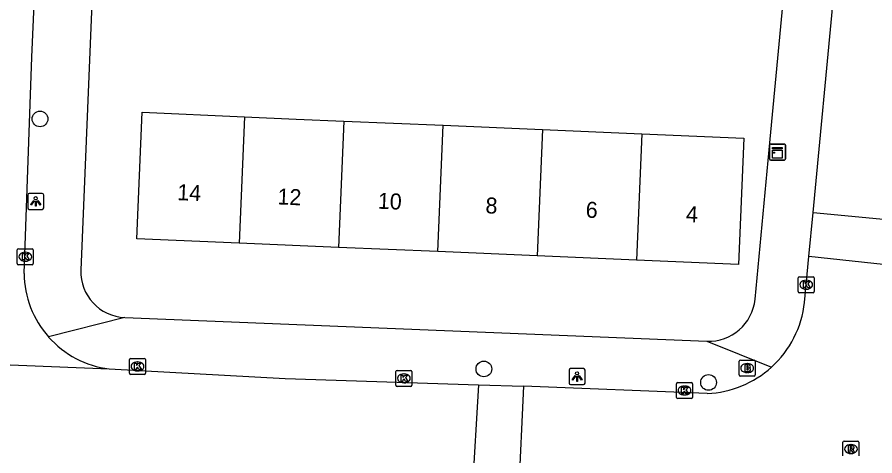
# Model space of a CAD drawing. Extents: x 161355 to 162026, y 386504 to 387459.
# Drawn here: x 161733.1 to 161786.7, y 386642.6 to 386670 of the extents above; entities that cross this region are included whole.
import ezdxf

# ---------------------------------------------------------------- set-up
doc = ezdxf.new("R2010")
doc.units = 0
for name, color, linetype in [('IMGEO_Boom', 7, 'Continuous'), ('IMGEO_Brandkraan', 7, 'Continuous'), ('IMGEO_Kast', 7, 'Continuous'), ('IMGEO_Kolk', 7, 'Continuous'), ('IMGEO_Lichtpunt', 7, 'Continuous'), ('IMGEO_Muur', 7, 'Continuous'), ('IMGEO_Pand', 7, 'Continuous'), ('IMGEO_Pand_nummerreeks', 7, 'Continuous'), ('IMGEO_Rijbaan_lokaal_open', 7, 'Continuous'), ('IMGEO_Rioolput', 7, 'Continuous'), ('IMGEO_Voetpad_open', 7, 'Continuous')]:
    doc.layers.add(name, color=color, linetype=linetype)

msp = doc.modelspace()

# ---------------------------------------------------------------- linework, layer by layer
at = {"layer": 'IMGEO_Boom'}
for centre in [(161734.57, 386663.656), (161762.276, 386648.038), (161776.299, 386647.194)]:
    msp.add_circle(centre, 0.489, dxfattribs=at)
at = {"layer": 'IMGEO_Brandkraan'}
for p, q in [((161778.287, 386648.59), (161779.139, 386648.59)), ((161778.212, 386647.664), (161778.212, 386648.516)), ((161778.7, 386648.37), (161778.725, 386648.37)), ((161779.213, 386648.516), (161779.213, 386647.664)), ((161779.139, 386647.59), (161778.287, 386647.59)), ((161778.723, 386647.81), (161778.698, 386647.81))]:
    msp.add_line(p, q, dxfattribs=at)
for points in [[(161778.287, 386648.59), (161779.139, 386648.59)], [(161778.212, 386647.664), (161778.212, 386648.516)], [(161778.56, 386648.29), (161778.56, 386647.89), (161778.773, 386647.89)], [(161778.791, 386648.29), (161778.56, 386648.29)], [(161778.739, 386648.209), (161778.685, 386648.209), (161778.685, 386648.133)], [(161778.685, 386648.133), (161778.738, 386648.133)], [(161778.747, 386648.057), (161778.685, 386648.057), (161778.685, 386647.976)], [(161779.213, 386648.516), (161779.213, 386647.664)], [(161779.139, 386647.59), (161778.287, 386647.59)], [(161778.685, 386647.976), (161778.747, 386647.976)]]:
    msp.add_lwpolyline(points, dxfattribs=at)
for centre, radius, start, end in [((161778.289, 386648.514), 0.0765, 91.552, 178.448), ((161778.289, 386648.514), 0.0765, 91.552, 178.448), ((161779.137, 386648.514), 0.0765, 1.552, 88.448), ((161779.137, 386648.514), 0.0765, 1.552, 88.448), ((161778.74, 386648.171), 0.0379, 267.8285, 90.9355), ((161778.748, 386648.016), 0.0404, 269.8759, 90.5077), ((161778.795, 386648.145), 0.145, 59.4692, 91.5367), ((161778.82, 386648.192), 0.0922, 285.5137, 58.1501), ((161778.825, 386648), 0.105, 301.3115, 78.989), ((161778.289, 386647.666), 0.0765, 181.552, 268.448), ((161778.289, 386647.666), 0.0765, 181.552, 268.448), ((161778.779, 386648.141), 0.251, 268.6676, 293.5347), ((161779.137, 386647.666), 0.0765, 271.552, 358.448), ((161779.137, 386647.666), 0.0765, 271.552, 358.448)]:
    msp.add_arc(centre, radius, start, end, dxfattribs=at)
for centre, major_axis, ratio, start_param, end_param in [((161778.699, 386648.09), (-0.387, 0.002), 0.722429, 4.712389, 7.853982), ((161778.724, 386648.09), (-0.39, 0.002), 0.717154, 1.570796, 4.712389)]:
    msp.add_ellipse(centre, major_axis=major_axis, ratio=ratio, start_param=start_param, end_param=end_param, dxfattribs=at)
at = {"layer": 'IMGEO_Kast'}
for p, q in [((161780.107, 386661.163), (161780.107, 386662.004)), ((161780.107, 386662.004), (161780.107, 386661.163)), ((161780.182, 386662.088), (161781.023, 386662.088)), ((161781.023, 386662.088), (161780.182, 386662.088)), ((161781.107, 386662.013), (161781.107, 386661.172)), ((161781.107, 386661.172), (161781.107, 386662.013)), ((161781.032, 386661.088), (161780.191, 386661.088)), ((161780.191, 386661.088), (161781.032, 386661.088))]:
    msp.add_line(p, q, dxfattribs=at)
for points in [[(161780.302, 386661.878), (161780.902, 386661.878), (161780.902, 386661.793), (161780.302, 386661.793), (161780.302, 386661.878)], [(161780.302, 386661.703), (161780.902, 386661.703), (161780.902, 386661.214), (161780.302, 386661.214), (161780.302, 386661.703)]]:
    msp.add_lwpolyline(points, dxfattribs=at)
msp.add_circle((161780.386, 386661.552), 0.0377, dxfattribs=at)
for centre, start, end in [((161780.185, 386662.01), 92.4484, 184.2845), ((161780.185, 386662.01), 92.4484, 184.2845), ((161781.029, 386662.01), 2.4484, 94.2845), ((161781.029, 386662.01), 2.4484, 94.2845), ((161780.185, 386661.166), 182.4484, 274.2845), ((161780.185, 386661.166), 182.4484, 274.2845), ((161781.029, 386661.166), 272.4484, 4.2845), ((161781.029, 386661.166), 272.4484, 4.2845)]:
    msp.add_arc(centre, 0.0779, start, end, dxfattribs=at)
at = {"layer": 'IMGEO_Kolk'}
for p, q in [((161733.227, 386655.546), (161734.079, 386655.546)), ((161733.152, 386654.62), (161733.152, 386655.472)), ((161733.64, 386655.326), (161733.665, 386655.326)), ((161734.153, 386655.472), (161734.153, 386654.62)), ((161734.079, 386654.546), (161733.227, 386654.546)), ((161733.663, 386654.766), (161733.638, 386654.766)), ((161781.896, 386652.876), (161781.896, 386653.728)), ((161781.971, 386653.802), (161782.823, 386653.802)), ((161782.384, 386653.582), (161782.409, 386653.582)), ((161782.897, 386653.728), (161782.897, 386652.876)), ((161782.407, 386653.022), (161782.382, 386653.022)), ((161782.823, 386652.802), (161781.971, 386652.802)), ((161740.154, 386647.771), (161740.154, 386648.623)), ((161740.229, 386648.697), (161741.081, 386648.697)), ((161741.155, 386648.623), (161741.155, 386647.771)), ((161740.642, 386648.477), (161740.667, 386648.477)), ((161741.081, 386647.697), (161740.229, 386647.697)), ((161740.665, 386647.917), (161740.64, 386647.917)), ((161756.783, 386647.026), (161756.783, 386647.878)), ((161756.858, 386647.952), (161757.71, 386647.952)), ((161757.271, 386647.732), (161757.296, 386647.732)), ((161757.784, 386647.878), (161757.784, 386647.026)), ((161757.294, 386647.172), (161757.269, 386647.172)), ((161774.3, 386646.266), (161774.3, 386647.118)), ((161774.375, 386647.192), (161775.227, 386647.192)), ((161774.788, 386646.972), (161774.813, 386646.972)), ((161775.301, 386647.118), (161775.301, 386646.266)), ((161757.71, 386646.952), (161756.858, 386646.952)), ((161775.227, 386646.192), (161774.375, 386646.192)), ((161774.811, 386646.412), (161774.786, 386646.412))]:
    msp.add_line(p, q, dxfattribs=at)
for points in [[(161733.227, 386655.546), (161734.079, 386655.546)], [(161733.152, 386654.62), (161733.152, 386655.472)], [(161733.473, 386655.246), (161733.596, 386655.246), (161733.596, 386655.095), (161733.726, 386655.246), (161733.89, 386655.246), (161733.744, 386655.095), (161733.897, 386654.846), (161733.745, 386654.846), (161733.66, 386655.01), (161733.596, 386654.943), (161733.596, 386654.846), (161733.473, 386654.846), (161733.473, 386655.246)], [(161734.153, 386655.472), (161734.153, 386654.62)], [(161734.079, 386654.546), (161733.227, 386654.546)], [(161781.896, 386652.876), (161781.896, 386653.728)], [(161781.971, 386653.802), (161782.823, 386653.802)], [(161782.217, 386653.502), (161782.34, 386653.502), (161782.34, 386653.351), (161782.47, 386653.502), (161782.634, 386653.502), (161782.488, 386653.351), (161782.641, 386653.102), (161782.489, 386653.102), (161782.404, 386653.266), (161782.34, 386653.199), (161782.34, 386653.102), (161782.217, 386653.102), (161782.217, 386653.502)], [(161782.897, 386653.728), (161782.897, 386652.876)], [(161782.823, 386652.802), (161781.971, 386652.802)], [(161740.154, 386647.771), (161740.154, 386648.623)], [(161740.229, 386648.697), (161741.081, 386648.697)], [(161741.155, 386648.623), (161741.155, 386647.771)], [(161740.475, 386648.397), (161740.598, 386648.397), (161740.598, 386648.246), (161740.728, 386648.397), (161740.892, 386648.397), (161740.746, 386648.246), (161740.899, 386647.997), (161740.747, 386647.997), (161740.662, 386648.161), (161740.598, 386648.094), (161740.598, 386647.997), (161740.475, 386647.997), (161740.475, 386648.397)], [(161741.081, 386647.697), (161740.229, 386647.697)], [(161756.783, 386647.026), (161756.783, 386647.878)], [(161756.858, 386647.952), (161757.71, 386647.952)], [(161757.104, 386647.652), (161757.227, 386647.652), (161757.227, 386647.501), (161757.357, 386647.652), (161757.521, 386647.652), (161757.375, 386647.501), (161757.528, 386647.252), (161757.376, 386647.252), (161757.291, 386647.416), (161757.227, 386647.349), (161757.227, 386647.252), (161757.104, 386647.252), (161757.104, 386647.652)], [(161757.784, 386647.878), (161757.784, 386647.026)], [(161774.3, 386646.266), (161774.3, 386647.118)], [(161774.375, 386647.192), (161775.227, 386647.192)], [(161775.301, 386647.118), (161775.301, 386646.266)], [(161757.71, 386646.952), (161756.858, 386646.952)], [(161774.621, 386646.892), (161774.744, 386646.892), (161774.744, 386646.741), (161774.874, 386646.892), (161775.038, 386646.892), (161774.892, 386646.741), (161775.045, 386646.492), (161774.893, 386646.492), (161774.808, 386646.656), (161774.744, 386646.589), (161774.744, 386646.492), (161774.621, 386646.492), (161774.621, 386646.892)], [(161775.227, 386646.192), (161774.375, 386646.192)]]:
    msp.add_lwpolyline(points, dxfattribs=at)
for centre, start, end in [((161733.229, 386655.47), 91.552, 178.448), ((161733.229, 386655.47), 91.552, 178.448), ((161734.077, 386655.47), 1.552, 88.448), ((161734.077, 386655.47), 1.552, 88.448), ((161733.229, 386654.622), 181.552, 268.448), ((161733.229, 386654.622), 181.552, 268.448), ((161734.077, 386654.622), 271.552, 358.448), ((161734.077, 386654.622), 271.552, 358.448), ((161781.973, 386653.726), 91.552, 178.448), ((161781.973, 386653.726), 91.552, 178.448), ((161782.821, 386653.726), 1.552, 88.448), ((161782.821, 386653.726), 1.552, 88.448), ((161781.973, 386652.878), 181.552, 268.448), ((161781.973, 386652.878), 181.552, 268.448), ((161782.821, 386652.878), 271.552, 358.448), ((161782.821, 386652.878), 271.552, 358.448), ((161740.231, 386648.621), 91.552, 178.448), ((161740.231, 386648.621), 91.552, 178.448), ((161741.079, 386648.621), 1.552, 88.448), ((161741.079, 386648.621), 1.552, 88.448), ((161740.231, 386647.773), 181.552, 268.448), ((161740.231, 386647.773), 181.552, 268.448), ((161741.079, 386647.773), 271.552, 358.448), ((161741.079, 386647.773), 271.552, 358.448), ((161756.86, 386647.876), 91.552, 178.448), ((161756.86, 386647.876), 91.552, 178.448), ((161757.708, 386647.876), 1.552, 88.448), ((161757.708, 386647.876), 1.552, 88.448), ((161756.86, 386647.028), 181.552, 268.448), ((161756.86, 386647.028), 181.552, 268.448), ((161757.708, 386647.028), 271.552, 358.448), ((161757.708, 386647.028), 271.552, 358.448), ((161774.377, 386647.116), 91.552, 178.448), ((161774.377, 386647.116), 91.552, 178.448), ((161775.225, 386647.116), 1.552, 88.448), ((161775.225, 386647.116), 1.552, 88.448), ((161774.377, 386646.268), 181.552, 268.448), ((161774.377, 386646.268), 181.552, 268.448), ((161775.225, 386646.268), 271.552, 358.448), ((161775.225, 386646.268), 271.552, 358.448)]:
    msp.add_arc(centre, 0.0765, start, end, dxfattribs=at)
for centre, major_axis, ratio, start_param, end_param in [((161733.639, 386655.046), (-0.387, 0.002), 0.722429, 4.712389, 7.853982), ((161733.664, 386655.046), (-0.39, 0.002), 0.717154, 1.570796, 4.712389), ((161782.383, 386653.302), (-0.387, 0.002), 0.722429, 4.712389, 7.853982), ((161782.408, 386653.302), (-0.39, 0.002), 0.717154, 1.570796, 4.712389), ((161740.641, 386648.197), (-0.387, 0.002), 0.722429, 4.712389, 7.853982), ((161740.666, 386648.197), (-0.39, 0.002), 0.717154, 1.570796, 4.712389), ((161757.27, 386647.452), (-0.387, 0.002), 0.722429, 4.712389, 7.853982), ((161757.295, 386647.452), (-0.39, 0.002), 0.717154, 1.570796, 4.712389), ((161774.787, 386646.692), (-0.387, 0.002), 0.722429, 4.712389, 7.853982), ((161774.812, 386646.692), (-0.39, 0.002), 0.717154, 1.570796, 4.712389)]:
    msp.add_ellipse(centre, major_axis=major_axis, ratio=ratio, start_param=start_param, end_param=end_param, dxfattribs=at)
at = {"layer": 'IMGEO_Lichtpunt'}
for p, q in [((161733.803, 386658.904), (161733.803, 386658.097)), ((161733.803, 386658.904), (161733.803, 386658.097)), ((161734.705, 386658.999), (161733.897, 386658.999)), ((161734.705, 386658.999), (161733.897, 386658.999)), ((161734.799, 386658.097), (161734.799, 386658.904)), ((161734.799, 386658.097), (161734.799, 386658.904)), ((161733.897, 386658.003), (161734.705, 386658.003)), ((161733.897, 386658.003), (161734.705, 386658.003)), ((161768.495, 386648.062), (161767.687, 386648.062)), ((161768.495, 386648.062), (161767.687, 386648.062)), ((161767.593, 386647.967), (161767.593, 386647.16)), ((161767.593, 386647.967), (161767.593, 386647.16)), ((161768.589, 386647.16), (161768.589, 386647.967)), ((161768.589, 386647.16), (161768.589, 386647.967)), ((161767.687, 386647.066), (161768.495, 386647.066)), ((161767.687, 386647.066), (161768.495, 386647.066))]:
    msp.add_line(p, q, dxfattribs=at)
for points in [[(161734.177, 386658.568), (161734.216, 386658.54), (161734.028, 386658.278), (161733.99, 386658.305), (161734.177, 386658.568)], [(161734.279, 386658.52), (161734.326, 386658.52), (161734.326, 386658.198), (161734.279, 386658.198), (161734.279, 386658.52)], [(161734.389, 386658.54), (161734.427, 386658.567), (161734.614, 386658.305), (161734.575, 386658.277), (161734.389, 386658.54)], [(161767.967, 386647.631), (161768.006, 386647.603), (161767.818, 386647.341), (161767.78, 386647.368), (161767.967, 386647.631)], [(161768.069, 386647.583), (161768.116, 386647.583), (161768.116, 386647.261), (161768.069, 386647.261), (161768.069, 386647.583)], [(161768.179, 386647.603), (161768.217, 386647.63), (161768.404, 386647.368), (161768.365, 386647.34), (161768.179, 386647.603)]]:
    msp.add_lwpolyline(points, dxfattribs=at)
for centre in [(161734.302, 386658.702), (161768.092, 386647.765)]:
    msp.add_circle(centre, 0.0994, dxfattribs=at)
for centre, start, end in [((161733.897, 386658.904), 90, 180), ((161733.897, 386658.904), 90, 180), ((161734.705, 386658.904), 0, 90), ((161734.705, 386658.904), 0, 90), ((161733.897, 386658.097), 180, 270), ((161733.897, 386658.097), 180, 270), ((161734.705, 386658.097), 270, 0), ((161734.705, 386658.097), 270, 360), ((161767.687, 386647.967), 90, 180), ((161767.687, 386647.967), 90, 180), ((161768.495, 386647.967), 0, 90), ((161768.495, 386647.967), 0, 90), ((161767.687, 386647.16), 180, 270), ((161767.687, 386647.16), 180, 270), ((161768.495, 386647.16), 270, 0), ((161768.495, 386647.16), 270, 360)]:
    msp.add_arc(centre, 0.0946, start, end, dxfattribs=at)
at = {"layer": 'IMGEO_Muur'}
msp.add_lwpolyline([(161780.147, 386662.39), (161781.003, 386671.42)], dxfattribs=at)
at = {"layer": 'IMGEO_Pand'}
for points in [[(161746.994, 386655.899), (161740.619, 386656.173), (161740.947, 386664.088), (161747.333, 386663.797)], [(161747.333, 386663.797), (161746.994, 386655.899)], [(161747.333, 386663.797), (161750.567, 386663.65), (161753.533, 386663.524)], [(161753.533, 386663.524), (161753.194, 386655.633)], [(161753.533, 386663.524), (161759.734, 386663.259)], [(161759.395, 386655.367), (161759.734, 386663.259)], [(161759.734, 386663.259), (161765.934, 386662.995)], [(161765.934, 386662.995), (161765.595, 386655.101)], [(161765.934, 386662.995), (161772.134, 386662.731)], [(161772.134, 386662.731), (161778.497, 386662.46), (161778.172, 386654.561), (161771.795, 386654.835)], [(161772.134, 386662.731), (161771.795, 386654.835)], [(161753.194, 386655.633), (161746.994, 386655.899)], [(161759.395, 386655.367), (161753.194, 386655.633)], [(161765.595, 386655.101), (161759.395, 386655.367)], [(161771.795, 386654.835), (161765.595, 386655.101)]]:
    msp.add_lwpolyline(points, dxfattribs=at)
at = {"layer": 'IMGEO_Rijbaan_lokaal_open'}
for points in [[(161733.581, 386653.996), (161734.07, 386667.509), (161735.471, 386699.54), (161735.824, 386708.256)], [(161782.825, 386657.818), (161784.094, 386671.248)], [(161782.564, 386655.061), (161782.825, 386657.818)], [(161782.825, 386657.818), (161789.606, 386657.165)], [(161782.294, 386652.199), (161782.564, 386655.061)], [(161789.315, 386654.342), (161782.564, 386655.061)], [(161720.322, 386648.852), (161720.876, 386648.777), (161738.887, 386648.046)], [(161738.887, 386648.046), (161749.864, 386647.448), (161761.932, 386647.046)], [(161761.932, 386647.046), (161761.539, 386640.379)], [(161761.932, 386647.046), (161764.753, 386646.956)], [(161764.753, 386646.956), (161764.44, 386640.258)], [(161776.22, 386646.498), (161764.753, 386646.956)]]:
    msp.add_lwpolyline(points, dxfattribs=at)
for centre, radius, start, end in [((161739.626, 386654.051), 6.046, 180.5173, 221.6217), ((161775.914, 386652.91), 6.42, 312.2122, 353.6422), ((161739.635, 386654.054), 6.055, 221.5933, 262.9009), ((161775.915, 386652.909), 6.418, 272.7236, 312.2092)]:
    msp.add_arc(centre, radius, start, end, dxfattribs=at)
at = {"layer": 'IMGEO_Rioolput'}
for p, q in [((161784.687, 386642.611), (161784.687, 386643.463)), ((161784.762, 386643.537), (161785.614, 386643.537)), ((161785.175, 386643.317), (161785.2, 386643.317)), ((161785.688, 386643.463), (161785.688, 386642.611)), ((161785.198, 386642.757), (161785.173, 386642.757))]:
    msp.add_line(p, q, dxfattribs=at)
for points in [[(161784.687, 386642.611), (161784.687, 386643.463)], [(161784.762, 386643.537), (161785.614, 386643.537)], [(161785.276, 386643.235), (161785.024, 386643.237), (161785.024, 386642.837)], [(161785.688, 386643.463), (161785.688, 386642.611)], [(161785.024, 386642.837), (161785.148, 386642.837), (161785.148, 386642.999), (161785.159, 386642.999)], [(161785.202, 386643.156), (161785.148, 386643.156), (161785.148, 386643.075)], [(161785.148, 386643.075), (161785.2, 386643.075)], [(161785.206, 386642.97), (161785.277, 386642.837), (161785.417, 386642.837), (161785.352, 386642.963)]]:
    msp.add_lwpolyline(points, dxfattribs=at)
for centre, radius, start, end in [((161784.764, 386643.461), 0.0765, 91.552, 178.448), ((161784.764, 386643.461), 0.0765, 91.552, 178.448), ((161785.275, 386643.125), 0.109, 350.3612, 89.416), ((161785.612, 386643.461), 0.0765, 1.552, 88.448), ((161785.612, 386643.461), 0.0765, 1.552, 88.448), ((161785.158, 386642.946), 0.0533, 26.0293, 88.6989), ((161785.184, 386643.264), 0.19, 274.7715, 282.9687), ((161785.208, 386643.06), 0.0964, 77.0061, 93.1865), ((161785.222, 386643.117), 0.0378, 276.6634, 79.6772), ((161785.273, 386643.125), 0.112, 277.5842, 350.9817), ((161785.257, 386642.91), 0.108, 29.5134, 73.7905)]:
    msp.add_arc(centre, radius, start, end, dxfattribs=at)
for centre, major_axis, ratio, start_param, end_param in [((161785.174, 386643.037), (-0.387, 0.002), 0.722429, 4.712389, 7.853982), ((161785.199, 386643.037), (-0.39, 0.002), 0.717154, 1.570796, 4.712389)]:
    msp.add_ellipse(centre, major_axis=major_axis, ratio=ratio, start_param=start_param, end_param=end_param, dxfattribs=at)
at = {"layer": 'IMGEO_Voetpad_open'}
for points in [[(161738.04, 386676.455), (161737.118, 386654.209)], [(161779.2, 386652.395), (161780.147, 386662.39), (161781.003, 386671.42)], [(161739.865, 386651.251), (161735.107, 386650.035)], [(161739.865, 386651.251), (161776.19, 386649.769)], [(161776.19, 386649.769), (161780.227, 386648.155)]]:
    msp.add_lwpolyline(points, dxfattribs=at)
for centre, radius, start, end in [((161739.978, 386654.11), 2.861, 178.0207, 267.7431), ((161776.307, 386652.672), 2.906, 267.6829, 354.5216)]:
    msp.add_arc(centre, radius, start, end, dxfattribs=at)

# ---------------------------------------------------------------- texts
at = {"layer": 'IMGEO_Pand_nummerreeks'}
for s, p in [('14', (161743.122, 386658.587)), ('12', (161749.378, 386658.319)), ('10', (161755.642, 386658.05)), ('8', (161762.362, 386657.762)), ('6', (161768.617, 386657.493)), ('4', (161774.876, 386657.225))]:
    msp.add_text(s, height=1, rotation=357.542, dxfattribs=at).set_placement(p)

doc.saveas('drawing.dxf')
